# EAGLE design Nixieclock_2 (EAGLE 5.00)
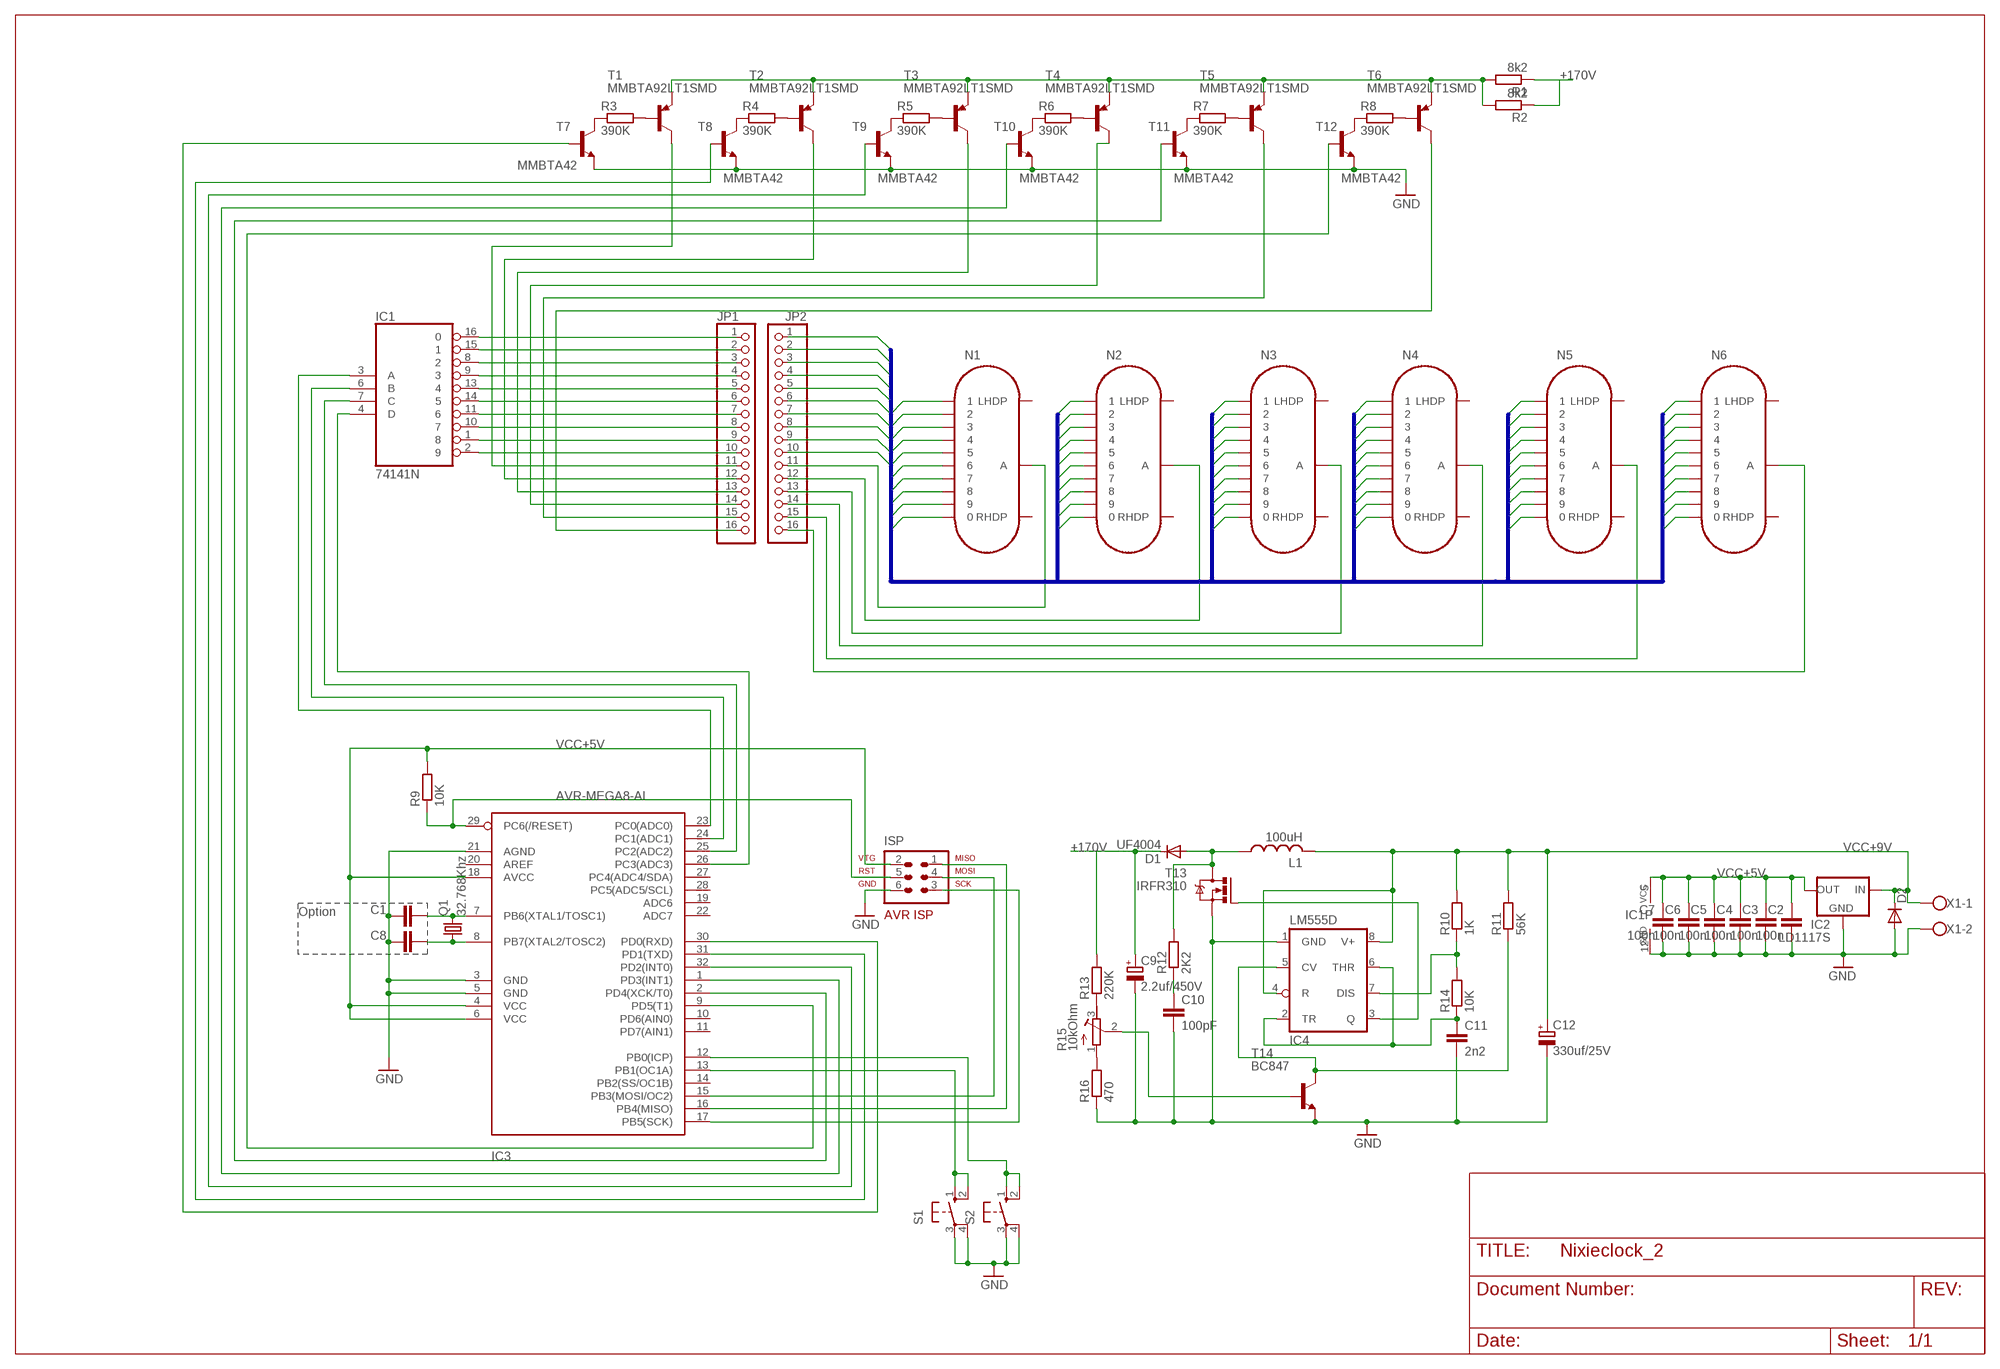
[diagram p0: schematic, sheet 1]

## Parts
C1  C-EUC0805  [C0805]
C2  100n  C-EUC0805  [C0805]
C3  100n  C-EUC0805  [C0805]
C4  100n  C-EUC0805  [C0805]
C5  100n  C-EUC0805  [C0805]
C6  100n  C-EUC0805  [C0805]
C7  100n  C-EUC0805  [C0805]
C8  C-EUC0805  [C0805]
C9  2.2uf/450V  CPOL-EUE3.5-8  [E3,5-8]
C10  100pF  C-EU025-030X050  [C025-030X050]
C11  2n2  C-EUC0805  [C0805]
C12  330uf/25V  CPOL-EUF  [PANASONIC_F]
D1  UF4004  1N4004  [DO41-10]
D2  DIODE-MELF-MLL41  [MELF-MLL41]
IC1  74141N  [DIL16]
IC2  LD1117S  [SOT223]
IC3  AVR-MEGA8-AI  [TQFP32-08]
IC4  LM555D  [SO08]
ISP  AVR-ISP-6  [AVR-ISP-6]
JP1  PINHD-1X16  [1X16]
JP2  PINHD-1X16  [1X16]
L1  100uH  L-USSQUARE12MM  [COILSQUARE12MM]
N1  IN-16  [IN-16]
N2  IN-16  [IN-16]
N3  IN-16  [IN-16]
N4  IN-16  [IN-16]
N5  IN-16  [IN-16]
N6  IN-16  [IN-16]
Q1  32.768Khz  CRYTALTC26H  [TC26H]
R1  8k2  R-EU_M0805  [M0805]
R2  8k2  R-EU_M0805  [M0805]
R3  390K  R-EU_M0805  [M0805]
R4  390K  R-EU_M0805  [M0805]
R5  390K  R-EU_M0805  [M0805]
R6  390K  R-EU_M0805  [M0805]
R7  390K  R-EU_M0805  [M0805]
R8  390K  R-EU_M0805  [M0805]
R9  10K  R-EU_M0805  [M0805]
R10  1K  R-EU_M0805  [M0805]
R11  56K  R-EU_M0805  [M0805]
R12  2K2  R-EU_M0805  [M0805]
R13  220K  R-EU_M0805  [M0805]
R14  10K  R-EU_M0805  [M0805]
R15  10kOhm  R-TRIMM3314J  [RTRIM3314J]
R16  470  R-EU_M0805  [M0805]
S1  10-XX  [B3F-10XX]
S2  10-XX  [B3F-10XX]
T1  MMBTA92LT1SMD  [SOT23-BEC]
T2  MMBTA92LT1SMD  [SOT23-BEC]
T3  MMBTA92LT1SMD  [SOT23-BEC]
T4  MMBTA92LT1SMD  [SOT23-BEC]
T5  MMBTA92LT1SMD  [SOT23-BEC]
T6  MMBTA92LT1SMD  [SOT23-BEC]
T7  MMBTA42  MMBTA42LT1-NPN-SOT23-BEC  [SOT23-BEC]
T8  MMBTA42  MMBTA42LT1-NPN-SOT23-BEC  [SOT23-BEC]
T9  MMBTA42  MMBTA42LT1-NPN-SOT23-BEC  [SOT23-BEC]
T10  MMBTA42  MMBTA42LT1-NPN-SOT23-BEC  [SOT23-BEC]
T11  MMBTA42  MMBTA42LT1-NPN-SOT23-BEC  [SOT23-BEC]
T12  MMBTA42  MMBTA42LT1-NPN-SOT23-BEC  [SOT23-BEC]
T13  IRFR310  [TO252]
T14  BC847  [SOT23]
X1  W237-102  [W237-102]

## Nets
+170V: C9.+ D1.C R1.1 R2.1 R13.2
D0: JP2.1 N1.0 N2.0 N3.0 N4.0 N5.0 N6.0
D1: JP2.2 N1.1 N2.1 N3.1 N4.1 N5.1 N6.1
D2: JP2.3 N1.2 N2.2 N3.2 N4.2 N5.2 N6.2
D3: JP2.4 N1.3 N2.3 N3.3 N4.3 N5.3 N6.3
D4: JP2.5 N1.4 N2.4 N3.4 N4.4 N5.4 N6.4
D5: JP2.6 N1.5 N2.5 N3.5 N4.5 N5.5 N6.5
D6: JP2.7 N1.6 N2.6 N3.6 N4.6 N5.6 N6.6
D7: JP2.8 N1.7 N2.7 N3.7 N4.7 N5.7 N6.7
D8: JP2.9 N1.8 N2.8 N3.8 N4.8 N5.8 N6.8
D9: JP2.10 N1.9 N2.9 N3.9 N4.9 N5.9 N6.9
GND [Vcc]: C1.1 C2.2 C3.2 C4.2 C5.2 C6.2 C7.2 C8.1 C9.- C10.2 C11.2 C12.- D2.A IC1.12(GND) IC2.1(GND) IC3.3(GND) IC3.5(GND) IC3.21(AGND) IC4.1(GND) ISP.6 R16.1 S1.3(P) S1.4(P1) S2.3(P) S2.4(P1) T7.E T8.E T9.E T10.E T11.E T12.E T13.2(S) T14.2(E) X1.2
N$1: IC1.4(D) IC3.26(PC3(ADC3))
N$2: IC1.7(C) IC3.25(PC2(ADC2))
N$3: IC1.6(B) IC3.24(PC1(ADC1))
N$4: IC1.3(A) IC3.23(PC0(ADC0))
N$5: R3.2 T1.B
N$6: R4.2 T2.B
N$7: R3.1 T7.C
N$8: R5.2 T3.B
N$9: R4.1 T8.C
N$10: R6.2 T4.B
N$11: R5.1 T9.C
N$12: R7.2 T5.B
N$13: R6.1 T10.C
N$14: R8.2 T6.B
N$15: R7.1 T11.C
N$16: R8.1 T12.C
N$17: JP1.14 T4.C
N$18: JP1.15 T5.C
N$19: JP2.13 N3.A
N$20: JP2.14 N4.A
N$21: JP2.15 N5.A
N$22: JP2.16 N6.A
N$23: R1.2 R2.2 T1.E T2.E T3.E T4.E T5.E T6.E
N$24: C1.2 IC3.7(PB6(XTAL1/TOSC1)) Q1.2
N$25: R15.1(E) R16.2
N$26: IC3.30(PD0(RXD)) T7.B
N$27: IC3.31(PD1(TXD)) T8.B
N$28: IC3.32(PD2(INT0)) T9.B
N$29: IC3.1(PD3(INT1)) T10.B
N$30: IC3.2(PD4(XCK/T0)) T11.B
N$31: IC3.9(PD5(T1)) T12.B
N$32: C8.2 IC3.8(PB7(XTAL2/TOSC2)) Q1.1
N$33: IC3.17(PB5(SCK)) ISP.3
N$34: IC3.15(PB3(MOSI/OC2)) ISP.4
N$35: IC3.16(PB4(MISO)) ISP.1
N$36: R13.1 R15.3(A)
N$38: C10.1 R12.1
N$39: D1.A L1.P$1 R12.2 T13.3(D)
N$40: R15.2(S) T14.1(B)
N$41: IC4.7(DIS) R10.1 R14.2
N$42: C11.1 IC4.2(TR) IC4.6(THR) R14.1
N$43: IC4.5(CV) R11.1 T14.3(C)
N$44: IC4.3(Q) T13.1(G)
N$45: IC3.13(PB1(OC1A)) S1.1(S) S1.2(S1)
N$46: IC3.12(PB0(ICP)) S2.1(S) S2.2(S1)
N$47: IC3.29(PC6(/RESET)) ISP.5 R9.1
N$48: IC1.16 JP1.1
N$49: IC1.15 JP1.2
N$50: IC1.8 JP1.3
N$51: IC1.9 JP1.4
N$52: IC1.13 JP1.5
N$53: IC1.14 JP1.6
N$54: IC1.11 JP1.7
N$55: IC1.10 JP1.8
N$56: IC1.1 JP1.9
N$57: IC1.2 JP1.10
N$58: JP1.11 T1.C
N$59: JP1.12 T2.C
N$60: JP1.16 T6.C
N$62: JP2.12 N2.A
N$63: JP2.11 N1.A
N$64: JP1.13 T3.C
VCC+5V [Vcc]: C2.1 C3.1 C4.1 C5.1 C6.1 C7.1 IC1.5(VCC) IC2.2(OUT) IC3.4(VCC) IC3.6(VCC) IC3.18(AVCC) ISP.2 R9.2
VCC+9V [Vcc]: C12.+ D2.C IC2.3(IN) IC4.4(R) IC4.8(V+) L1.P$2 R10.2 R11.2 X1.1
Unconnected: IC3.10(PD6(AIN0)) IC3.11(PD7(AIN1)) IC3.14(PB2(SS/OC1B)) IC3.19(ADC6) IC3.20(AREF) IC3.22(ADC7) IC3.27(PC4(ADC4/SDA)) IC3.28(PC5(ADC5/SCL)) N1.LHDP N1.RHDP N2.LHDP N2.RHDP N3.LHDP N3.RHDP N4.LHDP N4.RHDP N5.LHDP N5.RHDP N6.LHDP N6.RHDP

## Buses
D[0..9],LHDP,RHDP

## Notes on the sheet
- Option

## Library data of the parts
C1-C8 C10 C11 = rcl:C-EU: CAPACITOR, European symbol
C9 C12 = rcl:CPOL-EU: POLARIZED CAPACITOR, European symbol
D1 = diode:1N4004: DIODE
D2 = diode:DIODE-: DIODE
IC1 = 74xx-eu:74*141: BCD to decimal DECODER/DRIVER
IC2 = Evert:LD1117S
IC3 = SparkFun:AVR-MEGA8: MICROCONTROLLER 8 Kbytes FLASH 1 kbytes SRAM 512 bytes EEPROM USART 6-channel 10 bit ADC 2-channel 8 bit ADC
IC4 = linear:*555: TIMER
ISP = atmel:AVR-ISP-6: AVR ISP-6 Serial Programming Header
JP1 JP2 = pinhead:PINHD-1X16: PIN HEADER
L1 = Evert:L-US: INDUCTOR, American symbol
N1-N6 = russian-nixies:IN-16: IN-16: small numeric frontview nixie tube
Q1 = crystal:CRYTAL: CRYSTAL
R1-R14 R16 = rcl:R-EU_: RESISTOR, European symbol
R15 = resistor:R-TRIMM: Trimm resistor
S1 S2 = switch-omron:10-XX: OMRON SWITCH
T1-T6 = transistor-pnp:MMBTA92*: PNP Transistror
T7-T12 = transistor-neu-to92:*-NPN-: NPN Transistror
T13 = Evert:IRFR310
T14 = transistor:BC847: NPN TRANSISTOR
X1 = con-wago-500:W237-102: WAGO SCREW CLAMP

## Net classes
1 Vcc: width 0.559 mm, clearance 0.051 mm
2 Gnd: clearance 0.15 mm

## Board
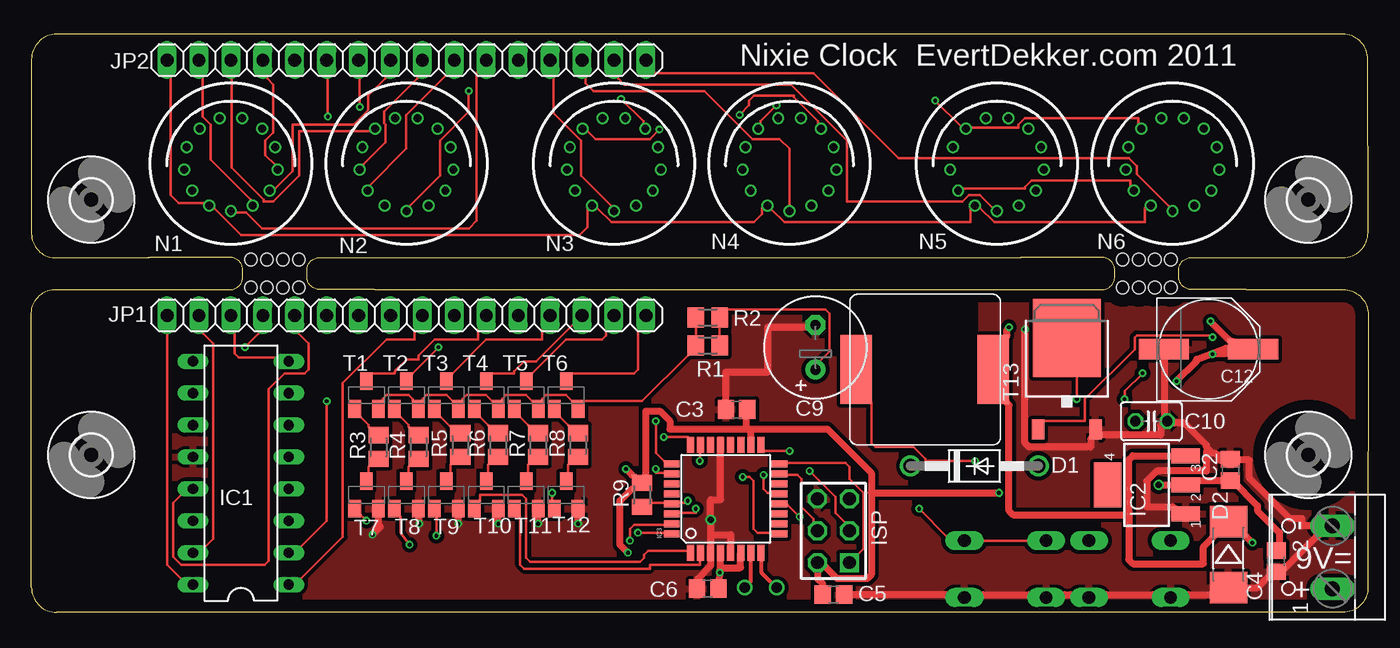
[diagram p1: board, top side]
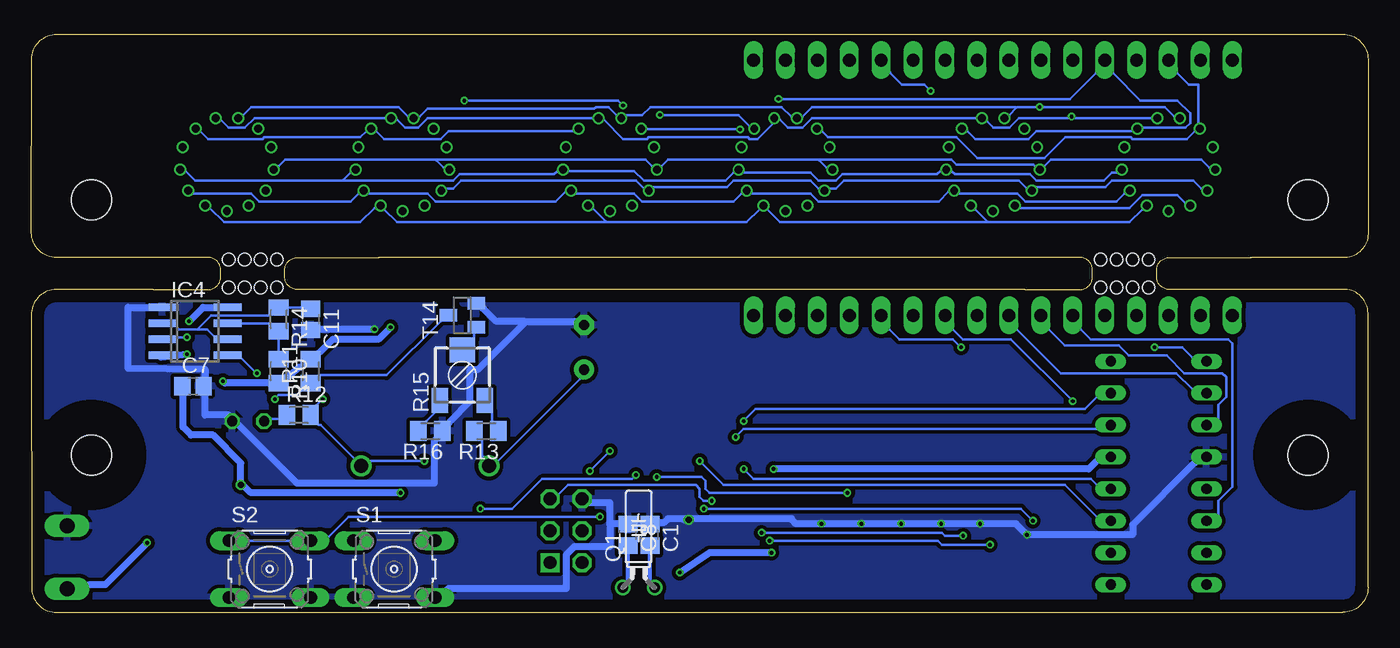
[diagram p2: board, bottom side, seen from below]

Size 106.36 x 46.02 mm. Coordinates in mm from the lower left corner, seen from the top.
Outline: 9.31,25.71 15.82,25.71 arc90 16.82,26.71 16.82,27.26 arc90 15.82,28.26 9.31,28.26
Outline: 27.3,28.26 22.92,28.26 arc90 21.92,27.26 21.92,26.71 arc90 22.92,25.71 27.3,25.71
Outline: 78.68,25.71 85.2,25.71 arc90 86.2,26.71 86.2,27.26 arc90 85.2,28.26 78.68,28.26
Outline: 96.67,28.26 92.3,28.26 arc90 91.3,27.26 91.3,26.71 arc90 92.3,25.71 96.67,25.71
Outline: 9.37,28.25 2,28.25 arc-93 0,30.14 0,44.03 arc-90 2,46.03 104.35,46.03 arc-90 106.35,44.03 106.36,30.25 arc-90 104.36,28.25 96.68,28.25
Outline: 9.37,25.71 2,25.71 arc93 0,23.81 0,2 arc90 2,0 104.35,0 arc92 106.35,2.06 106.36,23.65 arc92 104.36,25.71 96.68,25.71
Outline: 27.3,28.25 78.74,28.25
Outline: 27.3,25.71 78.74,25.71
Copper layers (1*16): Top 0.035mm / dielectric 1.5mm / Bottom 0.035mm
Design rules "MakePcb": minimum track width 0.2mm, minimum drill 0.3mm, track to track 0.2mm, track to pad 0.2mm, pad to pad 0.2mm, via to via 0.2mm, smd to smd 0.2mm, copper to edge 40mil, drill to drill 20mil, minimum pad ring 0.15mm, minimum via ring 0.15mm, stop-mask expansion 6mil, vias tented up to drill 0mil, thermal gap 10mil
Holes 1 mm at 17.46,25.87 18.73,25.87 20.01,25.87 21.28,25.87 17.46,28.1 18.73,28.1 20.01,28.1 21.28,28.1 86.83,25.87 88.11,25.87 89.38,25.87 90.66,25.87 86.83,28.1 88.11,28.1 89.38,28.1 90.66,28.1

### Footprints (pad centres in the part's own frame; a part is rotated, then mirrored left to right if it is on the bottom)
C0805 = smd 1.3 x 1.5: 1 -0.85,0; 2 0.85,0
E3,5-8 = drill 0.813 pad 1.6 round: + -1.778,0 | drill 0.813 pad 1.6 octagon: - 1.778,0
C025-030X050 = drill 0.813 octagon: 1 -1.27,0; 2 1.27,0
PANASONIC_F = smd 4 x 1.6: + 3.55,0; - -3.55,0
DO41-10 = drill 1.118 round: A 5.08,0; C -5.08,0
MELF-MLL41 = smd 2.5 x 3: A 2.625,0; C -2.625,0
DIL16 = drill 0.813 long: 1 -8.89,-3.81; 2 -6.35,-3.81; 3 -3.81,-3.81; 4 -1.27,-3.81; 5 1.27,-3.81; 6 3.81,-3.81; 7 6.35,-3.81; 8 8.89,-3.81; 9 8.89,3.81; 10 6.35,3.81; 11 3.81,3.81; 12 1.27,3.81; 13 -1.27,3.81; 14 -3.81,3.81; 15 -6.35,3.81; 16 -8.89,3.81
SOT223 = smd 1.219 x 2.235: 1 -2.311,-3.099; 2 0,-3.099; 3 2.311,-3.099 | smd 3.6 x 2.2: 4 0,3.099
TQFP32-08 = smd 1.27 x 0.559: 1 -4.293,2.8; 2 -4.293,2; 3 -4.293,1.2; 4 -4.293,0.4; 5 -4.293,-0.4; 6 -4.293,-1.2; 7 -4.293,-2; 8 -4.293,-2.8; 17 4.293,-2.8; 18 4.293,-2; 19 4.293,-1.2; 20 4.293,-0.4; 21 4.293,0.4; 22 4.293,1.2; 23 4.293,2; 24 4.293,2.8 | smd 0.559 x 1.27: 9 -2.8,-4.293; 10 -2,-4.293; 11 -1.2,-4.293; 12 -0.4,-4.293; 13 0.4,-4.293; 14 1.2,-4.293; 15 2,-4.293; 16 2.8,-4.293; 25 2.8,4.293; 26 2,4.293; 27 1.2,4.293; 28 0.4,4.293; 29 -0.4,4.293; 30 -1.2,4.293; 31 -2,4.293; 32 -2.8,4.293
SO08 = smd 0.6 x 2.2: 1 -1.905,-2.6; 2 -0.635,-2.6; 3 0.635,-2.6; 4 1.905,-2.6; 5 1.905,2.6; 6 0.635,2.6; 7 -0.635,2.6; 8 -1.905,2.6
AVR-ISP-6 = drill 1.016 square: 1 -2.54,-1.27 | drill 1.016 octagon: 2 -2.54,1.27; 3 0,-1.27; 4 0,1.27; 5 2.54,-1.27; 6 2.54,1.27
1X16 = drill 1.016 long: 1 -19.05,0; 2 -16.51,0; 3 -13.97,0; 4 -11.43,0; 5 -8.89,0; 6 -6.35,0; 7 -3.81,0; 8 -1.27,0; 9 1.27,0; 10 3.81,0; 11 6.35,0; 12 8.89,0; 13 11.43,0; 14 13.97,0; 15 16.51,0; 16 19.05,0
COILSQUARE12MM = smd 2.5 x 5.5: P$1 -5.5,0; P$2 5.4,0
IN-16 = drill 0.63 round: 0 -1.745,-3.325; 1 1.745,-3.325; 2 -2.49,2.81; 3 3.727,-0.453; 4 2.49,2.81; 5 0.898,3.645; 6 -0.898,3.645; 7 3.09,-2.133; 8 -3.727,-0.453; 9 -3.09,-2.133; A 0,-3.755; LHDP -3.511,1.331; RHDP 3.511,1.331
TC26H = drill 0.813 round: 1 -1.27,0; 2 1.27,0
M0805 = smd 1.3 x 1.6: 1 -0.95,0; 2 0.95,0
RTRIM3314J = smd 1.3 x 2: 1 -1.8,-2; 3 1.8,-2 | smd 2 x 2: 2 0,2
B3F-10XX = drill 1.016 long: 1 -3.251,2.261; 2 3.251,2.261; 3 -3.251,-2.261; 4 3.251,-2.261
SOT23-BEC = smd 1 x 1.4: B -0.95,-1.1; C 0,1.1; E 0.95,-1.1
TO252 = smd 1 x 1.6: 1 -2.28,-4.8; 2 2.28,-4.8 | smd 5.4 x 6.2: 3 0,2.5
SOT23 = smd 1 x 1.4: 1 -0.95,-1.1; 2 0.95,-1.1; 3 0,1.1
3,2 = hole 3.2: 0,0
W237-102 = drill 1.194 long: 1 -2.5,-1.27; 2 2.5,-1.27

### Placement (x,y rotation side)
C1  57.15,6.19 270 bottom
C2  95.41,11.34 90 top
C3  56.12,16.15 180 top
C4  99.04,4.08 270 top
C5  63.82,1.42 0 top
C6  53.82,1.9 180 top
C7  93.5,18.01 0 bottom
C8  58.9,6.18 270 bottom
C9  62.39,21.11 90 top
C10  89.12,15.22 0 top
C11  84.14,23.33 270 bottom
C12  93.66,20.95 0 top
D1  75.04,11.66 0 top
D2  95.25,4.6 270 top
IC1  16.67,11.11 90 top
IC2  88.74,10.15 90 top
IC3  55.24,9.04 90 top
IC4  93.34,22.38 270 bottom
ISP  63.82,6.5 90 top
JP1  29.84,23.65 0 top
JP2  29.84,43.97 0 top
L1  71.12,19.33 0 top
N1  15.87,35.71 0 top
N2  29.84,35.71 0 top
N3  46.35,35.71 0 top
N4  60.32,35.71 0 top
N5  76.83,35.71 0 top
N6  90.8,35.71 0 top
Q1  58.04,1.97 0 bottom
R1  53.82,21.27 180 top
R2  53.82,23.49 180 top
R3  27.62,13.17 90 top
R4  30.8,13.17 90 top
R5  34.13,13.33 90 top
R6  37.15,13.33 90 top
R7  40.32,13.33 90 top
R8  43.5,13.33 90 top
R9  48.58,9.36 90 top
R10  86.68,19.2 270 bottom
R11  84.14,19.2 90 bottom
R12  85.09,15.71 0 bottom
R13  70.17,14.44 180 bottom
R14  86.68,23.33 270 bottom
R15  72.07,18.88 0 bottom
R16  74.61,14.44 180 bottom
S1  77.5,3.45 0 bottom
S2  87.4,3.45 0 bottom
T1  26.67,17.3 0 top
T2  29.84,17.3 0 top
T3  33.02,17.3 0 top
T4  36.19,17.3 0 top
T5  39.37,17.3 0 top
T6  42.54,17.3 0 top
T7  26.67,9.36 0 top
T8  29.84,9.36 0 top
T9  33.02,9.36 0 top
T10  36.19,9.36 0 top
T11  39.37,9.36 0 top
T12  42.54,9.36 0 top
T13  82.39,19.36 0 top
T14  72.07,23.65 90 bottom
U$1  [3,2]  4.76,32.85 0 top
U$2  [3,2]  101.6,32.85 0 top
U$3  [3,2]  4.76,12.53 0 top
U$4  [3,2]  101.6,12.53 0 top
X1  102.25,4.39 90 top

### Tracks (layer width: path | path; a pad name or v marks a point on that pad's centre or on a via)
+170V
  Top 0.2: R1.1 54.77,22.06 54.77,22.7 R2.1 55.4,24.12 63.18,24.12 63.5,23.81 63.5,20.79 62.71,20 C9.+
  Bottom 0.2: R13.2 70.48,13.65 70.48,12.38 70.33,12.38 D1.C 69.21,12.06 62.71,18.57 C9.+
D0
  Top 0.2: JP2.1 11.09,42.54 11.09,33.23 11.72,32.59 13.77,32.59 N1.0 14.53,32.21 16.7,30.04 43.6,30.04 44.24,30.68 44.24,32.21 N3.0 45,32.21 46.15,31.06 57.5,31.06 58.14,31.7 58.14,32.21 N4.0 58.9,32.08 59.92,31.06 74.71,31.06 74.71,32.21 N5.0 75.48,32.21 76.62,31.06 88.61,31.06 88.61,32.21 N6.0
  Bottom 0.2: N2.0 27.66,32.21 18.99,32.21 17.97,33.23 15.17,33.23 14.53,32.59 N1.0
D1
  Top 0.2: N1.1 17.46,32.84 14.28,36.03 14.28,38.84 13.64,39.48 13.64,42.54 JP2.2
  Bottom 0.2: N6.1 92.18,32.21 91.03,31.06 80.19,31.06 79.05,32.21 N5.1 78.28,32.08 77.26,31.06 60.69,31.06 60.62,31.12 | 60.62,31.12 61.71,32.21 N4.1 | 60.62,31.12 60.56,31.06 49.47,31.06 48.45,32.08 N3.1 47.81,32.08 46.79,31.06 30.34,31.06 30.28,31.12 | 30.28,31.12 30.21,31.06 18.99,31.06 17.97,32.08 N1.1 | 30.28,31.12 31.23,32.08 N2.1
D2  (via drill 0.3)
  Top 0.2: N6.2 88.1,38.96 88.1,39.35 79.05,39.35 78.54,38.84 78.54,38.58 74.71,38.58 N5.2 73.95,38.71 v71.91,40.75 | N2.2 26.9,38.33 21.29,38.33 21.29,34.76 19.25,32.72 18.48,32.72 18.48,32.84 15.93,35.4 15.93,42.54 JP2.3 | v49.98,38.45 49.21,37.69 44.87,37.69 44.24,38.32 44.24,38.33 N3.2 | v59.28,40.37 58.01,39.09 58.01,38.96 N4.2
  Bottom 0.2: JP2.3 15.17,42.92 14.28,42.03 13.51,42.03 13.51,38.96 N1.2 13.77,38.33 14.4,37.69 18.74,37.69 18.87,37.82 24.09,37.82 25.75,36.16 31.11,36.16 32.76,37.82 42.96,37.82 43.47,38.33 N3.2 | v49.98,38.45 57.37,38.45 N4.2 | v71.91,40.75 59.67,40.75 v59.28,40.37
D3
  Top 0.2: N1.3 19.38,35.65 18.61,36.42 18.61,37.56 19.25,38.2 19.25,42.03 18.74,42.54 JP2.4
  Bottom 0.2: N1.3 20.01,35.01 20.4,35.01 21.03,34.37 26.39,34.37 26.9,34.89 32.89,34.89 33.15,35.14 N2.3 34.04,35.14 34.29,34.89 41.82,34.89 42.33,34.37 43.73,34.37 44.37,35.01 49.72,35.01 N3.3 50.49,35.01 51.12,34.37 57.63,34.37 58.39,35.14 63.62,35.14 N4.3 64.51,35.14 64.77,34.89 72.29,34.89 72.8,34.37 81.47,34.37 81.53,34.44 | 81.53,34.44 81.6,34.37 93.33,34.37 94.09,35.14 N6.3 | 81.53,34.44 80.96,35.01 N5.3
D4  (via drill 0.3)
  Top 0.2: v56.35,39.6 57.12,40.37 57.12,40.75 57.5,41.13 60.69,41.13 60.69,41.01 62.6,39.09 62.6,38.96 N4.4 | v46.92,40.88 48.7,39.09 48.7,38.96 N3.4
  Bottom 0.2: N2.4 31.87,38.33 31.23,37.69 27.03,37.69 26.39,38.33 18.74,38.33 N1.4 17.97,38.58 14.53,38.58 14.15,38.96 14.15,39.73 15.17,40.75 18.1,40.75 20.27,42.92 JP2.5 21.67,42.92 23.71,40.88 v46.92,40.88 | N6.4 92.94,38.33 92.31,37.69 87.97,37.69 87.84,37.82 80.19,37.82 79.68,38.33 N5.4 78.92,38.33 78.28,37.69 73.82,37.69 73.18,38.33 63.24,38.33 N4.4 | v56.35,39.6 50.1,39.6 49.21,38.71 N3.4
D5  (via drill 0.3)
  Top 0.2: v23.58,39.48 23.58,42.54 JP2.6
  Bottom 0.2: N6.5 91.29,39.22 90.65,38.58 89.37,38.58 88.61,39.35 78.15,39.35 N5.5 77.26,39.22 76.62,38.58 75.6,38.58 74.84,39.35 61.58,39.35 N4.5 60.81,39.22 59.28,37.69 57.37,37.69 57.24,37.82 49.34,37.82 49.21,37.69 48.57,37.69 47.3,38.96 N3.5 46.79,39.22 46.15,38.58 45,38.58 44.24,39.35 31.11,39.35 N2.5 30.34,39.09 29.83,38.58 28.56,38.58 27.79,39.35 23.58,39.35 | 23.58,39.35 17.21,39.35 N1.5 | 23.58,39.35 v23.58,39.48
D6  (via drill 0.3)
  Top 0.2: v26.13,40.24 26.13,42.54 JP2.7
  Bottom 0.2: N6.6 89.5,39.6 88.86,40.24 77.13,40.24 76.37,39.48 N5.6 75.48,39.48 74.84,40.11 61.58,40.11 61.45,40.24 60.43,40.24 59.79,39.6 N4.6 59.03,39.6 57.75,39.6 57.12,40.24 46.66,40.24 45.9,39.48 N3.6 45,39.48 44.24,40.24 28.05,40.24 27.98,40.18 | 27.98,40.18 28.56,39.6 N2.6 | 27.98,40.18 27.92,40.24 v26.13,40.24 16.19,40.24 15.42,39.48 N1.6
D7
  Top 0.2: JP2.8 28.17,42.54 26.77,41.13 26.77,39.98 25.62,38.84 20.78,38.84 20.78,35.14 19.38,33.74 N1.7
  Bottom 0.2: N1.7 19.38,33.35 20.01,32.72 27.28,32.72 27.92,33.35 32.51,33.35 N2.7 33.4,33.48 34.17,32.72 43.73,32.72 44.37,33.35 49.08,33.35 N3.7 49.85,33.35 50.49,32.72 57.75,32.72 58.39,33.35 62.98,33.35 N4.7 63.87,33.48 64.64,32.72 74.2,32.72 74.84,33.35 79.56,33.35 N5.7 80.32,33.35 80.96,32.72 88.23,32.72 88.86,33.35 93.45,33.35 N6.7
D8
  Top 0.2: JP2.9 30.72,42.54 28.05,39.86 28.05,38.96 28.17,38.84 28.17,37.43 26.39,35.65 N2.8
  Bottom 0.2: N1.8 12.62,35.4 13.26,36.03 25.24,36.03 25.75,35.52 N2.8 26.52,35.52 26.64,35.65 32.76,35.65 33.15,36.03 43.6,36.03 43.67,35.97 | 43.67,35.97 43.73,36.03 55.71,36.03 56.22,35.52 N4.8 56.99,35.52 57.5,36.03 74.07,36.03 74.14,35.97 | 43.67,35.97 43.09,35.4 N3.8 | 74.14,35.97 74.2,36.03 86.19,36.03 86.7,35.52 N6.8 | 74.14,35.97 73.56,35.4 N5.8
D9
  Top 0.2: JP2.10 33.02,42.79 29.83,39.6 29.83,36.93 26.9,33.99 N2.9 | N5.9 74.2,33.74 79.05,33.74 79.05,33.87 79.56,34.37 87.46,34.37 87.46,33.99 N6.9
  Bottom 0.2: N1.9 13.26,33.74 13.89,34.37 20.4,34.37 20.91,33.87 26.39,33.87 N2.9 27.15,33.74 27.79,34.37 41.69,34.37 42.33,33.74 42.84,33.74 N3.9 43.73,33.74 44.37,34.37 50.49,34.37 51,33.87 56.86,33.87 N4.9 57.63,33.74 58.26,34.37 72.16,34.37 72.8,33.74 73.31,33.74 N5.9
GND  (via drill 0.3, 0.5)
  Top 0.559: v27.15,6.18 27.62,6.66 27.78,6.82 27.62,6.82 T7.E | C5.2 65.25,1.42 72.87,1.42 S1.4 75.72,1.42 79.37,1.42 S1.3 82.23,1.42 82.71,1.42 S2.4 85.57,1.42 89.22,1.42 S2.3 92.07,1.42 93.82,1.42 D2.A 97.55,1.97 98.9,3.33 98.99,3.23 C4.2 99.69,3.49 102.23,6.03 X1.2 101.12,6.89 101.12,7.46 100.17,7.46 96.92,10.71 96.92,12.14 94.54,12.14 94.54,12.11 C2.2 93.98,12.69 93.66,13.01 | C9.- 61.59,22.7 58.58,22.7 58.58,19.12 55.24,19.12 55.24,16.15 | v79.06,22.54 79.06,13.49 79.37,13.17 84.3,13.17 84.3,13.81 T13.2 85.09,14.12 89.85,14.12 89.85,14.92 C10.2 | 93.66,13.01 93.5,13.17 93.5,13.33 91.76,15.07 90.96,15.07 C10.2 | C12.- 90.17,20.15 90.17,15.71 C10.2 | T8.E v30.88,7.06 | T9.E v33.97,7.06 | T10.E v37.15,7.06 | T11.E v40.32,7.06 | T12.E 43.49,7.3 43.5,7.3 v43.5,7.06 | 54.05,6.18 v54.05,7.38 54.05,8.96 54.85,8.96 IC3.21 | 54.05,6.18 IC3.3 | IC3.5 55.64,6.18 54.05,6.18 | IC3.3 | IC3.3 54.05,3.72 53.02,2.69 53.02,1.98 52.94,1.9 | 52.94,1.9 | 52.94,1.9 C6.2 | 55.24,16.15 55.24,16.03 | 55.24,16.15 C3.2 | IC2.1 90.8,8.41 88.74,8.41 88.74,10.47 89.53,11.27 93.5,11.27 93.5,12.85 93.66,13.01
  Bottom 0.559: ISP.6 61.91,8.72 60.32,8.72 60.32,6.98 | 45.88,7.46 46.2,7.46 54.45,7.46 | IC1.12 13.81,11.9 18.73,6.98 18.73,6.18 v27.15,6.18 27.3,6.34 28.02,7.06 v30.88,7.06 v33.97,7.06 v37.15,7.06 v40.32,7.06 v43.5,7.06 45.56,7.06 45.88,7.46 | 45.88,7.46 | 67.15,23.17 63.18,23.17 C9.- | 67.15,23.17 69.37,23.17 70.33,24.12 T14.2 | 67.15,23.17 67.15,23.01 70.8,19.36 71.44,19.36 71.44,16.82 73.02,15.23 R16.1 74.29,13.65 74.29,10.31 85.25,10.31 89.85,14.92 C10.2 90.65,15.71 92.55,15.71 92.55,19.36 | v79.06,22.54 83.5,22.54 C11.2 | 92.55,19.36 92.55,17.85 C7.2 | IC4.1 98.66,24.28 98.66,19.44 92.55,19.36 | 60.32,6.98 60.32,5.23 63.18,5.23 63.82,4.6 63.82,1.9 73.18,1.9 S1.4 | 54.45,7.46 55.72,7.46 56.04,7.14 57.15,7.14 | 57.15,7.14 | 57.15,7.14 C1.1 58.84,7.04 58.9,6.98 C8.1 60.32,7.03 60.32,6.98 | v54.05,7.38 54.45,7.38 54.45,7.46
  pour Bottom (isolate 0.305): 0.32,25.08 105.89,25.08 105.89,0.39 0.32,0.39
  pour Top (isolate 0.305): 0.79,25.08 105.89,25.08 105.89,0.55 0.79,0.55
N$1  (via drill 0.3)
  Top 0.2: v49.69,11.42 49.69,11.11 50.32,11.11 IC3.26
  Bottom 0.2: v49.69,11.42 48.89,10.63 22.07,10.63 21.59,10.15 IC1.4
N$2  (via drill 0.3)
  Top 0.2: v49.69,15.23 49.69,12.69 50.32,12.06 IC3.25
  Bottom 0.2: v49.69,15.23 48.74,16.19 22.54,16.19 21.59,17.14 IC1.7
N$3  (via drill 0.3)
  Top 0.2: v50.32,13.96 52.23,13.96 IC3.24
  Bottom 0.2: v50.32,13.96 49.69,14.6 21.59,14.6 IC1.6
N$4  (via drill 0.3)
  Top 0.2: v53.18,12.06 53.18,12.85 IC3.23
  Bottom 0.2: v53.18,12.06 51.28,10.15 24.13,10.15 21.59,7.61 IC1.3
N$5
  Top 0.2: T1.B 26.19,15.55 26.83,14.92 26.83,14.76 R3.2
N$6
  Top 0.2: T2.B 29.37,15.55 30,14.92 30,14.76 R4.2
N$7
  Top 0.2: T7.C 26.83,11.11 26.83,11.58 R3.1
N$8
  Top 0.2: T3.B 32.54,15.55 33.34,14.76 R5.2
N$9
  Top 0.2: T8.C 30,11.11 30,11.58 R4.1
N$10
  Top 0.2: T4.B 35.72,15.55 36.35,14.92 R6.2
N$11
  Top 0.2: T9.C 33.34,11.11 33.34,11.74 R5.1
N$12
  Top 0.2: T5.B 38.89,15.55 39.53,14.92 R7.2
N$13
  Top 0.2: T10.C 36.35,11.11 36.35,11.74 R6.1
N$14
  Top 0.2: T6.B 42.07,15.55 42.7,14.92 R8.2
N$15
  Top 0.2: T11.C 39.53,11.11 39.53,11.74 R7.1
N$16
  Top 0.2: T12.C 42.7,11.11 42.7,11.74 R8.1
N$17
  Top 0.2: T4.C 36.67,19.04 38.42,19.04 38.42,19.2 39.21,20 40.16,20 JP1.14
N$18
  Top 0.2: T5.C 39.85,19.04 42.54,21.74 45.4,21.74 45.72,22.06 45.72,22.54 JP1.15
N$19
  Top 0.2: N3.A 46.15,32.34 43.73,34.76 43.73,37.56 41.56,39.73 41.56,42.54 JP2.13
N$20
  Top 0.2: N4.A 60.3,32.34 60.3,36.93 59.54,37.69 57.37,37.69 53.55,41.51 44.75,41.51 44.11,42.15 44.11,42.54 JP2.14
N$21
  Top 0.2: N5.A 76.5,32.21 75.48,33.23 74.58,33.23 74.07,32.72 64.89,32.72 64.89,37.56 60.43,42.03 47.17,42.03 46.66,42.54 JP2.15
N$22
  Top 0.2: N6.A 90.52,32.34 87.97,34.89 87.97,35.52 87.33,36.16 68.97,36.16 62.22,42.92 49.59,42.92 JP2.16
N$23
  Top 0.2: R2.2 52.86,22.7 52.86,22.06 R1.2 52.23,20.47 48.58,16.82 43.97,16.82 T6.E 43.02,16.82 42.54,17.3 40.96,17.3 40.64,16.98 40.64,16.82 T5.E 39.85,16.82 39.37,17.3 37.78,17.3 37.46,16.98 37.46,16.82 T4.E 36.67,16.82 36.19,17.3 34.61,17.3 34.29,16.98 34.29,16.82 T3.E 33.5,16.82 33.02,17.3 31.43,17.3 31.11,16.98 31.11,16.82 T2.E 30.32,16.82 30.32,16.98 30,17.3 28.26,17.3 27.94,16.98 27.94,16.82 T1.E
N$24
  Top 0.305: Q1.2 56.77,1.99 57.24,2.47 IC3.7
  Bottom 0.305: Q1.2 56.77,1.99 57.15,2.38 C1.2
N$25
  Bottom 0.2: R16.2 74.93,15.23 74.14,16.03 R15.1
N$26  (via drill 0.3)
  Top 0.2: v52.86,8.25 52.86,7.93 51.43,7.93 IC3.30 | v26.67,7.3 26.19,7.77 T7.B
  Bottom 0.2: v52.86,8.25 27.62,8.25 v26.67,7.3
N$27  (via drill 0.3)
  Top 0.2: v47.62,5.71 47.62,6.66 47.94,6.98 50.32,6.98 IC3.31 | v30.08,5.39 29.37,6.34 29.37,7.61 T8.B
  Bottom 0.2: v30.08,5.39 33.89,5.39 34.21,5.71 v47.62,5.71
N$28  (via drill 0.3)
  Top 0.2: v48.26,6.34 50.32,6.34 IC3.32 | v32.23,6.11 32.23,7.61 T9.B
  Bottom 0.2: v32.23,6.11 33.65,6.11 33.89,6.34 v48.26,6.34
N$29
  Top 0.2: IC3.1 52.23,4.92 51.28,4.92 49.05,4.92 48.74,4.6 48.74,4.36 48.42,4.04 39.69,4.04 39.37,4.36 39.37,9.04 39.05,9.36 35.72,9.36 35.72,8.88 T10.B
N$30
  Top 0.2: IC3.2 53.18,4.12 53.18,3.8 49.21,3.8 49.21,3.49 39.21,3.49 38.89,3.8 38.89,7.61 T11.B
N$31  (via drill 0.3)
  Top 0.2: v56.59,10.79 57.15,10.79 57.47,10.47 57.47,6.66 57.78,6.34 59.05,6.34 IC3.9 | v41.43,9.52 41.43,8.88 T12.B
  Bottom 0.2: v56.59,10.79 53.02,10.79 52.7,10.47 52.7,9.84 52.39,9.52 v41.43,9.52
N$32
  Top 0.305: Q1.1 58.1,3.17 58.1,4.76 58.1,4.75 IC3.8
  Bottom 0.305: Q1.1 59.37,1.9 | Q1.1 | C8.2 58.9,2.38 Q1.1
N$33  (via drill 0.3)
  Top 0.2: v60.32,12.85 58.26,12.85 IC3.17 | v61.91,11.27 63.98,9.2 63.98,7.93 64.77,7.14 ISP.3
  Bottom 0.2: v61.91,11.27 v60.32,12.85
N$34
  Top 0.2: IC3.15 60.17,10.95 60.96,10.95 61.28,10.63 61.28,8.41 62.23,7.46 62.23,7.14 ISP.4
N$35
  Top 0.2: IC3.16 60.17,11.9 64.77,11.9 65.09,11.58 65.09,10.63 66.2,9.52 66.2,5.07 65.72,4.6 ISP.1
N$36
  Bottom 0.2: R13.1 69.69,15.23 69.69,16.03 R15.3
N$38
  Bottom 0.2: R12.1 86.68,15.39 87.31,15.39 C10.1
N$39  (via drill 0.3)
  Top 0.2: v83.18,16.98 83.18,18.89 T13.3 | v75.09,12.06 71.12,12.06 71.12,12.22 70.17,13.17 67.15,13.17 66.83,13.49 66.83,16.66 L1.P$1
  Bottom 0.2: v83.18,16.98 83.66,16.5 R12.2 83.5,14.92 83.34,14.92 80.64,12.22 D1.A 79.37,12.06 v75.09,12.06
N$40
  Bottom 0.2: T14.1 71.12,22.22 71.12,21.74 R15.2
N$41
  Bottom 0.2: R10.1 R14.2 87.47,23.01 IC4.7
N$42
  Bottom 0.2: C11.1 84.77,24.28 85.88,24.28 R14.1 87.47,23.65 92.07,23.65 93.19,22.54 | 93.19,22.54 94.61,22.54 94.93,22.85 IC4.2 | 93.19,22.54 92.39,22.54 91.76,21.9 IC4.6
N$43  (via drill 0.3)
  Top 0.2: v88.42,19.04 86.99,17.61 v86.99,16.98
  Bottom 0.2: T14.3 73.82,23.17 78.1,18.89 83.34,18.89 R11.1 84.93,17.61 85.25,17.3 86.68,17.3 v86.99,16.98 | v88.42,19.04 89.69,20.31 IC4.5
N$44  (via drill 0.3)
  Top 0.2: v93.98,21.9 93.98,22.06 87.95,22.06 87.79,21.9 87.79,20.95 83.82,16.98 83.82,15.23 80.49,15.23 T13.1
  Bottom 0.2: v93.98,21.9 94.93,21.9 IC4.3
N$45  (via drill 0.3)
  Top 0.2: v58.26,10.95 58.26,9.84 58.58,9.52 59.05,9.52 IC3.13 | v70.64,8.25 72.87,6.03 S1.2 75.72,5.71 79.37,5.71 S1.1
  Bottom 0.2: v58.26,10.95 58.58,10.63 65.72,10.63 68.1,8.25 v70.64,8.25
N$46  (via drill 0.3)
  Top 0.2: v61.12,7.61 60.17,8.57 IC3.12
  Bottom 0.2: v61.12,7.61 81.12,7.61 82.71,6.03 S2.2 85.57,5.71 89.22,5.71 S2.1
N$47  (via drill 0.3)
  Top 0.2: R9.1 49.37,8.72 50.32,8.72 IC3.29 51.43,8.72 52.23,8.72 v52.23,8.88
  Bottom 0.2: v52.23,8.88 52.86,8.88 53.18,9.2 53.18,9.84 53.5,10.15 63.66,10.15 64.45,9.36 ISP.5
N$48
  Top 0.2: IC1.16 11.91,2.69 10.79,3.8 JP1.1
N$49
  Top 0.2: IC1.15 13.81,5.23 14.45,5.87 14.45,21.43 13.65,22.22 JP1.2
N$50
  Top 0.2: IC1.8 19.37,20.31 16.51,20.31 16.19,20.63 16.19,22.22 JP1.3
N$51  (via drill 0.3)
  Top 0.2: v16.99,21.11 18.1,22.22 JP1.4
  Bottom 0.2: v16.99,21.11 14.76,21.11 13.97,20.31 IC1.9
N$52
  Top 0.2: IC1.13 11.91,9.36 11.27,8.72 11.27,4.44 11.91,3.8 18.57,3.8 18.89,4.12 18.89,17.77 20.16,19.04 21.75,19.04 22.07,19.36 22.07,21.43 21.27,22.22 JP1.5
N$53
  Bottom 0.2: IC1.14 11.91,7.77 11.91,8.88 10.79,9.99 10.79,21.43 11.11,21.74 22.07,21.74 22.86,22.54 JP1.6
N$54
  Bottom 0.2: IC1.11 11.91,15.39 11.91,16.5 11.27,17.14 11.27,18.73 11.59,19.04 14.6,19.04 16.03,20.47 19.05,20.47 19.84,21.27 24.13,21.27 25.4,22.54 JP1.7
N$55
  Bottom 0.2: IC1.10 13.97,17.77 15.24,19.04 24.45,19.04 27.94,22.54 JP1.8
N$56
  Top 0.2: IC1.1 21.43,2.69 24.76,6.03 24.76,18.25 28.26,21.74 30.48,21.74 30.48,22.54 JP1.9
N$57  (via drill 0.3)
  Top 0.2: v23.49,16.82 23.49,7.3 21.43,5.23 IC1.2
  Bottom 0.2: v23.49,16.82 28.42,21.74 32.23,21.74 33.02,22.54 JP1.10
N$58
  Top 0.2: T1.C 27.15,19.04 28.89,19.04 28.89,19.07 28.99,19.3 29.84,20.15 30.8,20.15 30.8,20.47 32.07,21.74 35.56,21.74 35.56,22.54 JP1.11
N$59  (via drill 0.3)
  Top 0.2: v32.38,21.11 30.32,19.04 T2.C
  Bottom 0.2: v32.38,21.11 33.02,21.74 37.31,21.74 38.1,22.54 JP1.12
N$60
  Top 0.2: T6.C 43.02,19.04 47.94,19.04 48.26,19.36 48.26,22.54 JP1.16
N$62  (via drill 0.3)
  Top 0.2: v34.8,41.51 34.8,39.86 32.51,37.56 32.51,34.76 30.09,32.34 N2.A
  Bottom 0.2: v34.8,41.51 35.31,42.03 37.1,42.03 37.99,42.92 JP2.12
N$63
  Top 0.2: N1.A 16.32,31.82 17.08,31.82 18.36,30.55 34.81,30.55 35.44,31.18 35.44,42.92 JP2.11
N$64
  Top 0.2: T3.C 33.5,19.04 36.19,21.74 40.64,21.74 40.64,22.54 JP1.13
VCC+5V  (via drill 0.3, 0.5)
  Top 0.559: C6.1 v54.77,3.17 54.85,3.57 | R9.2 48.89,10.95 48.89,16.03 50.01,16.03 50.8,15.23 50.8,14.6 56.91,14.6 | v47.31,11.42 47.78,10.95 R9.2 | v47.47,4.76 46.83,5.39 46.83,8.88 47.78,9.84 R9.2 | IC3.4 54.85,3.57 | IC3.6 56.44,3.57 54.85,3.57 | C5.1 62.97,2.27 62.55,2.69 ISP.2 | ISP.2 62.55,4.04 | IC3.18 57.23,13.34 57.23,14.6 | 56.91,14.6 57.23,14.6 | 56.91,14.6 57.15,14.52 | C3.1 56.91,16.15 56.91,14.6 | C4.1 99.12,4.93 99.14,4.92 99.3,5.07 99.3,6.34 97.55,8.09 97.55,8.49 95.54,10.49 C2.1 92,10.49 92,10.15 IC2.2 v89.69,10.15 | v89.69,10.15 | 66.83,9.52 66.83,11.11 63.34,14.6 57.23,14.6 | 66.83,9.52 66.83,3.01 66.52,2.69 64.13,2.69 63.18,3.64 ISP.2 | 66.83,9.52 v76.99,9.52
  Bottom 0.559: v47.31,11.42 22.22,11.42 21.59,12.06 IC1.5 | v47.47,4.76 52.39,4.76 v54.77,3.17 | 94.46,18.33 94.38,17.93 C7.1 94.3,18.01 | v76.99,9.52 88.9,9.52 89.38,9.99 v89.69,10.15 89.69,11.9 91.92,14.12 93.66,14.12 94.3,14.76 94.3,18.01 | 94.3,18.01 94.22,18.09
VCC+9V  (via drill 0.3)
  Top 0.559: v97.15,5.55 96.68,6.03 D2.C 93.27,5.23 93.27,3.88 87.63,3.88 87.31,4.21 87.32,7.77 | v93.82,23.17 95.25,21.74 C12.+ | v93.98,20.55 96.12,20.63 C12.+ | v77.79,22.7 77.63,22.54 77.63,22.06 L1.P$2 77.63,16.66 77.79,16.5 77.79,8.09 78.1,7.77 86.99,7.77 87.31,8.09 87.32,7.77 | v91.12,18.41 92.71,20 92.71,20.15 95.01,21.03 C12.+ | 87.31,7.77 | 87.32,7.77 87.31,7.77 | 87.31,7.77 87.31,12.15 87.63,12.47 IC2.3
  Bottom 0.559: v97.15,5.55 100.49,2.22 101.76,2.22 X1.1 | v93.82,23.17 92.71,24.28 IC4.8 | v93.98,20.55 96.04,20.31 IC4.4 | v77.79,22.7 78.74,21.74 82.39,21.74 83.34,20.79 R11.2 84.93,19.52 85.09,19.52 85.72,18.89 85.88,18.89 R10.2 87.47,18.25 90.96,18.25 v91.12,18.41

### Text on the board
tNames: Nixie Clock EvertDekker.com 2011 | - | 9V= | +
